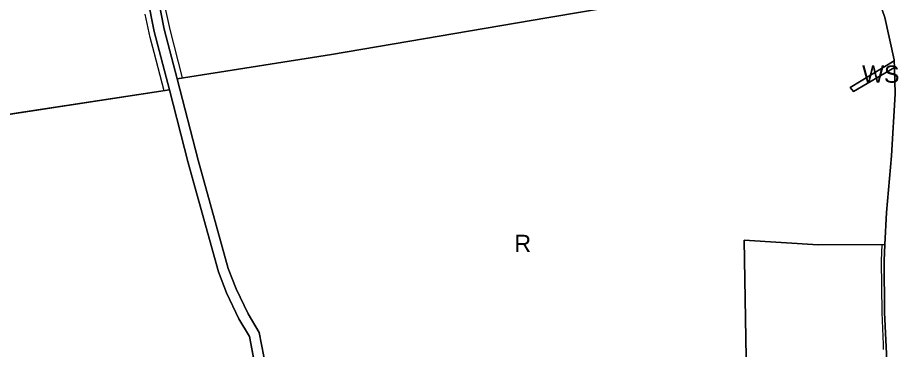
# Model space of a CAD drawing. Extents: x 7417187 to 7419415, y 5539178 to 5540826.
# Drawn here: x 7417708 to 7418217, y 5540006 to 5540198 of the extents above; entities that cross this region are included whole.
import ezdxf

# ---------------------------------------------------------------- set-up
doc = ezdxf.new("R2010")
doc.units = 0
for name, color, linetype in [('linie_rozgraniczajace', 7, 'Continuous'), ('linie_zabudowy_nieprzekraczalne', 7, 'Continuous'), ('oznaczenia_przeznaczen', 7, 'Continuous')]:
    doc.layers.add(name, color=color, linetype=linetype)

msp = doc.modelspace()

# ---------------------------------------------------------------- linework, layer by layer
at = {"layer": 'linie_rozgraniczajace'}
for p, q in [((7418209.21, 5540197.77), (7418202.33, 5540217.9)), ((7418214.67, 5540173.28), (7418209.21, 5540197.77)), ((7418214.68, 5540172.71), (7418214.67, 5540173.28)), ((7418214.78, 5540168.87), (7418214.68, 5540172.71)), ((7418215.15, 5540153.62), (7418214.78, 5540168.87)), ((7417577.64, 5540122.76), (7417795.7, 5540155.94)), ((7417795.7, 5540155.94), (7417806.44, 5540113.79)), ((7418213.05, 5540117.81), (7418215.15, 5540153.62)), ((7418210.27, 5540085), (7418213.05, 5540117.81)), ((7417806.44, 5540113.79), (7417823.98, 5540050.75)), ((7418209.26, 5540066.42), (7418210.27, 5540085)), ((7418208.83, 5540057.09), (7418209.26, 5540066.42)), ((7418209.09, 5540027.1), (7418208.83, 5540057.09)), ((7417823.98, 5540050.75), (7417828.75, 5540038.49)), ((7417828.75, 5540038.49), (7417835.87, 5540023.53)), ((7418210.59, 5539995.36), (7418209.09, 5540027.1)), ((7417835.87, 5540023.53), (7417841.94, 5540013.34)), ((7417841.94, 5540013.34), (7417845.64, 5539993.82))]:
    msp.add_line(p, q, dxfattribs=at)
for points in [[(7417795.7, 5540155.94), (7417577.64, 5540122.76), (7417576.76, 5540134.39), (7417572.43, 5540156.87), (7417578.8, 5540158.49), (7417620.25, 5540170.49), (7417633.16, 5540175.08), (7417644.77, 5540181.84), (7417655.03, 5540190.71), (7417666.1, 5540198.14), (7417692.17, 5540208.43), (7417769.63, 5540229.24), (7417777.04, 5540226.64), (7417782.96, 5540209.35), (7417786.82, 5540189.84)], [(7418214.78, 5540168.87), (7418191.19, 5540155.01), (7418189.15, 5540157.43), (7418214.68, 5540172.71)]]:
    msp.add_lwpolyline(points, close=True, dxfattribs=at)
for points in [[(7418202.33, 5540217.9), (7418209.21, 5540197.77), (7418214.67, 5540173.28), (7418214.68, 5540172.71), (7418189.15, 5540157.43), (7418191.19, 5540155.01), (7418214.78, 5540168.87), (7418215.15, 5540153.62), (7418213.05, 5540117.81), (7418210.27, 5540085), (7418209.26, 5540066.42), (7418170.64, 5540066.36), (7418127.97, 5540068.95), (7418129.52, 5539978.31)], [(7418103.26, 5540212.86), (7418013.89, 5540197.63), (7417889.44, 5540176.43), (7417800.23, 5540162.32), (7417792.67, 5540191.18), (7417788.76, 5540210.91)], [(7417788.76, 5540210.91), (7417792.67, 5540191.18), (7417800.23, 5540162.32), (7417812.24, 5540115.33), (7417829.68, 5540052.65), (7417834.26, 5540040.87), (7417841.16, 5540026.36), (7417847.64, 5540015.5), (7417851.57, 5539994.72)], [(7417851.57, 5539994.72), (7417847.64, 5540015.5), (7417841.16, 5540026.36), (7417834.26, 5540040.87), (7417829.68, 5540052.65), (7417812.24, 5540115.33), (7417800.23, 5540162.32), (7417889.44, 5540176.43), (7418013.89, 5540197.63), (7418103.26, 5540212.86)], [(7417845.64, 5539993.82), (7417841.94, 5540013.34), (7417835.87, 5540023.53), (7417828.75, 5540038.49), (7417823.98, 5540050.75), (7417806.44, 5540113.79), (7417795.7, 5540155.94), (7417786.82, 5540189.84), (7417782.96, 5540209.35)], [(7418129.52, 5539978.31), (7418127.97, 5540068.95), (7418170.64, 5540066.36), (7418209.26, 5540066.42), (7418208.83, 5540057.09), (7418209.09, 5540027.1), (7418210.59, 5539995.36)]]:
    msp.add_lwpolyline(points, dxfattribs=at)
at = {"layer": 'linie_zabudowy_nieprzekraczalne'}
for points in [[(7417790.75, 5540214.55), (7417795.86, 5540190.83)], [(7417784.65, 5540186.28), (7417781.72, 5540199.81)], [(7417795.86, 5540190.83), (7417803.15, 5540163.02)], [(7417792.72, 5540155.49), (7417786.91, 5540177.68), (7417784.65, 5540186.28)], [(7418208.46, 5540008.7), (7418207.59, 5540027.06), (7418207.33, 5540057.12), (7418207.76, 5540066.41)]]:
    msp.add_lwpolyline(points, dxfattribs=at)
msp.add_arc((7418187.32, 5540007.68), 21.17, 354.876, 2.7616, dxfattribs=at)

# ---------------------------------------------------------------- texts
at = {"layer": 'oznaczenia_przeznaczen'}
for s, p in [('WS', (7418196.13, 5540160.09)), ('R', (7417995.12, 5540062.11))]:
    msp.add_text(s, height=10, dxfattribs=at).set_placement(p)

doc.saveas('drawing.dxf')
